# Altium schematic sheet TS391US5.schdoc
size 127 x 101 mm
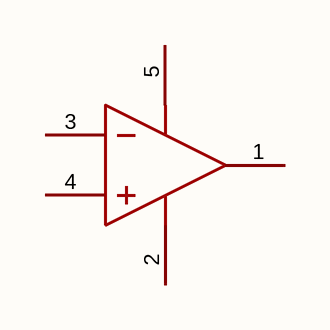
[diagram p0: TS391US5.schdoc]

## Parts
U?  ts391us5  [SOT-23-5_L3.0-W1.6-P0.95-LS2.8-BR]  (value not drawn)

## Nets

Not connected (* = marked no-connect by the designer): U? 1(OUT) 2(V-) 3(-IN) 4(+IN) 5(V+)

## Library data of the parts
U? = ts391us5: 比较器数:1;输入失调电压(Vos):2mV;; Manufacturer: TECH PUBLIC(台舟); AddInBom: yes; ModelId: 72410e292833493f86746b22636ce101; ModelTransform: 110.236,116.1415,0,0,0,0,0.002,0.001,0; Number of Channels: 1; Vos - Input Offset Voltage: 2mV; Output Type: 开路漏极; Output Mode: CMOS；ECL；DTL；TTL; Quiescent Current: 400uA; Single Supply: 2V~36V; Dual Supply: -18V~-1V；1V~18V; Input Offset Voltage Drift(Vos TC): 1uV/℃; Input Offset Current(Ios): 250nA; Response Time (tr): 1.3us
